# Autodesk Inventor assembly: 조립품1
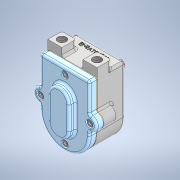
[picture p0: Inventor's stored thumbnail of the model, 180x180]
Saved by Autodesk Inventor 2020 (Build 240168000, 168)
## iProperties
Created: 2024-03
Part Number: 조립품1
Document SubType Name: Assembly
Designer: oem
Author: oem
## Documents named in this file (9)
- C:\Users\oem\Desktop\740304V1020\조립품1.iam
- C:\Users\oem\Desktop\740304V1020\본체.ipt
- C:\Users\oem\Desktop\740304V1020\오일레스 부시.ipt
- C:\Users\oem\Desktop\740304V1020\구동기어.ipt
- C:\Users\oem\Desktop\740304V1020\스퍼기어.ipt
- C:\Users\oem\Desktop\740304V1020\오일 실 14 25 7.ipt
- C:\Users\oem\Desktop\740304V1020\커버.ipt
- C:\Users\oem\Desktop\740304V1020\가스켓.ipt
- C:\Users\oem\Desktop\740304V1020\육각 소켓 머리 볼트 M5x12.ipt
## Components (2 placed, 2 different names)
1. 구동기어:1
2. 가스켓:1
